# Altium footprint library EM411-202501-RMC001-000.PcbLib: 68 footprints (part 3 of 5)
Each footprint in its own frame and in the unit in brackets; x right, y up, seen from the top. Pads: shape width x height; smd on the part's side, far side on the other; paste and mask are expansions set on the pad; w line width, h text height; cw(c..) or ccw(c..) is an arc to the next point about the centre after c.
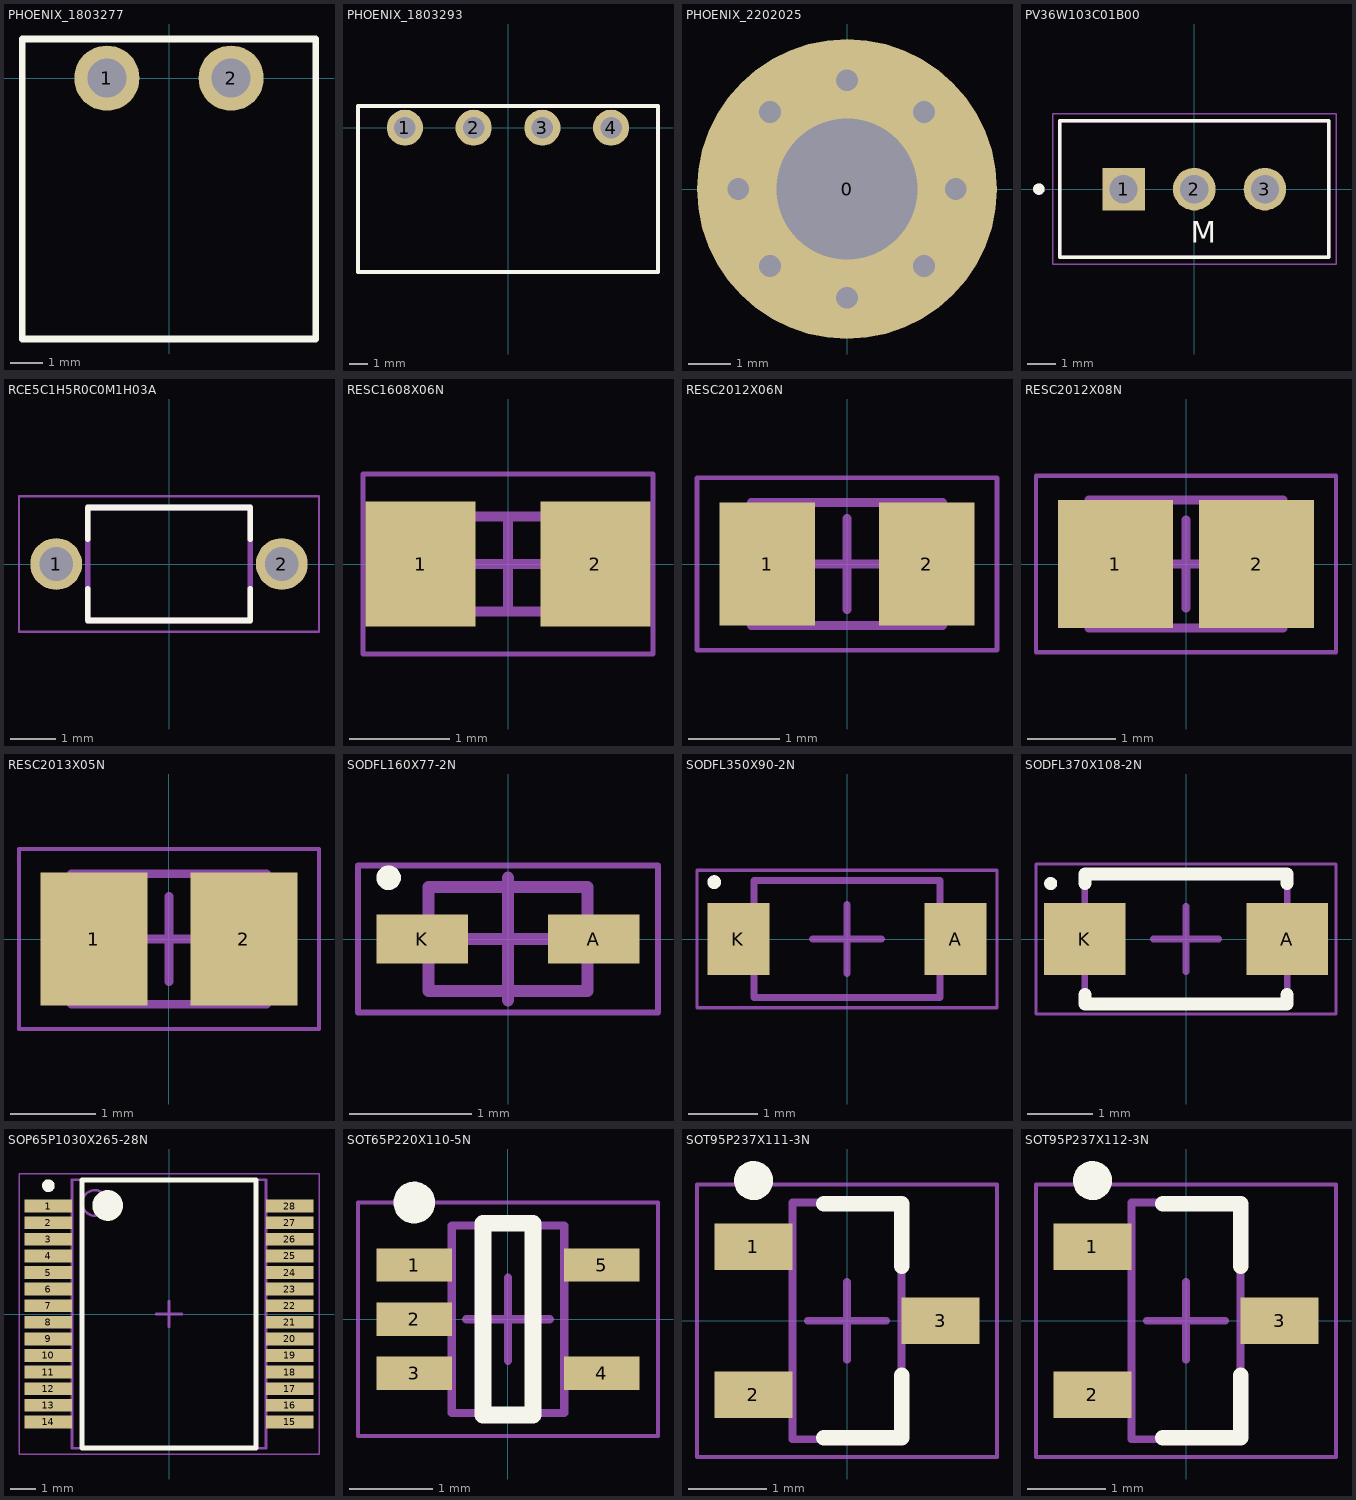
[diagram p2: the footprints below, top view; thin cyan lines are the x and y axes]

## PHOENIX_1803277 [mm] "PCB header - MC 1,5/ 2-G-3,81"
height 7.25
pads (2):
  round 2 hole 1.2: 1(-1.905,0) 2(1.905,0)
Top Overlay:
  lines w0.2: -4.505,-8 4.505,-8 4.505,1.2 -4.505,1.2 -4.505,-8
3D body "pxc_1803277_05_MC-1-5-2-G-3-81_3D.stp": height 7.25, standoff -3.4, extent -4.505,-8 4.505,1.3

## PHOENIX_1803293 [mm] "PCB header - MC 1,5/ 4-G-3,81"
height 7.25
pads (4):
  round 2 hole 1.2: 1(-5.715,0) 2(-1.905,0) 3(1.905,0) 4(5.715,0)
Top Overlay:
  lines w0.2: -8.315,-8 8.315,-8 8.315,1.2 -8.315,1.2 -8.315,-8
3D body "pxc_1803293_05_MC-1-5-4-G-3-81_3D.stp": height 7.25, standoff -3.4, extent -8.315,-8 8.315,1.3

## PHOENIX_2202025 [mm] "PE Contact Level 1"
height 8
pads (1):
  round 7 hole 3.3: 0(0,0)
via 1.796,-1.796 diameter 1.016 hole 0.508
via 2.54,0 diameter 1.016 hole 0.508
via -1.796,-1.796 diameter 1.016 hole 0.508
via 0,-2.54 diameter 1.016 hole 0.508
via -1.796,1.796 diameter 1.016 hole 0.508
via -2.54,0 diameter 1.016 hole 0.508
via 1.796,1.796 diameter 1.016 hole 0.508
via 0,2.54 diameter 1.016 hole 0.508

## PV36W103C01B00 [mm]
pads (3):
  rect 1.508x1.508 / inner round 1.508 / far side rect 1.508x1.508 hole 1: 1(-2.5,0)
  round 1.508 hole 1: 2(0,0) 3(2.5,0)
Top Overlay:
  circle w0.2: c-5.5,0 r0.1
  lines w0.127: -4.765,-2.41 4.765,-2.41 4.765,2.42 -4.765,2.42 -4.765,-2.41
  text "M" at -0.127,-1.905 h0.76
Mechanical 13:
  circle w0.2: c-5.5,0 r0.1
  lines w0.127: -4.765,-2.41 4.765,-2.41 4.765,2.42 -4.765,2.42 -4.765,-2.41
Mechanical 15:
  lines w0.05: -5.015,-2.66 5.015,-2.66 5.015,2.67 -5.015,2.67 -5.015,-2.66
3D body "step_temp.STEP": height 11.55, standoff -7.72, extent -4.765,-2.41 4.765,2.42

## RCE5C1H5R0C0M1H03A [mm] "5 pF ±0.25pF 50V Ceramic Capacitor C0G, NP0 Radial"
pads (2):
  round 1.15 hole 0.75: 1(-2.5,0) 2(2.5,0)
Top Overlay:
  lines w0.127: -1.8,-0.547 -1.8,-1.25 1.8,-1.25 1.8,-0.547 ; -1.8,0.547 -1.8,1.25 1.8,1.25 1.8,0.547
Mechanical 13:
  lines w0.127: -1.8,-1.25 1.8,-1.25 1.8,1.25 -1.8,1.25 -1.8,-1.25
Mechanical 15:
  lines w0.05: -3.325,-1.5 3.325,-1.5 3.325,1.5 -3.325,1.5 -3.325,-1.5

## RESC1608X06N [mm] "Chip Resistor, 2-Leads, Body 1.60x0.85mm, IPC Medium Density"
height 0.55
pads (2):
  rect 1.1x1.25 smd: 1(-0.875,0) 2(0.875,0)
Top Courtyard:
  lines w0.05: -1.45,-0.9 1.45,-0.9 1.45,0.9 -1.45,0.9 -1.45,-0.9
  lines w0.1: -0.475,0 0.475,0 ; 0,-0.475 0,0.475
Mechanical 13:
  lines w0.1: -0.85,-0.475 0.85,-0.475 0.85,0.475 -0.85,0.475 -0.85,-0.475
3D body "RESC1608X06N.step": height 0.55, standoff 0, extent -0.85,-0.475 0.85,0.475

## RESC2012X06N [mm] "Chip Resistor, 2-Leads, Body 2.00x1.25mm, IPC Medium Density"
height 0.6
pads (2):
  rect 1.05x1.35 smd: 1(-0.875,0) 2(0.875,0)
Top Courtyard:
  lines w0.05: -1.65,-0.95 -1.65,0.95 1.65,0.95 1.65,-0.95 -1.65,-0.95
  lines w0.1: -0.5,0 0.5,0 ; 0,-0.5 0,0.5
Mechanical 13:
  lines w0.1: -1.05,-0.675 -1.05,0.675 1.05,0.675 1.05,-0.675 -1.05,-0.675
3D body "RESC2012X06N.step": height 0.6, standoff 0, extent -1.05,-0.675 1.05,0.675

## RESC2012X08N [mm] "Chip Resistor, 2-Leads, Body 2.00x1.25mm, IPC Medium Density"
height 0.75
pads (2):
  rect 1.3x1.45 smd: 1(-0.8,0) 2(0.8,0)
Top Courtyard:
  lines w0.05: -1.7,-1 1.7,-1 1.7,1 -1.7,1 -1.7,-1
  lines w0.1: -0.5,0 0.5,0 ; 0,-0.5 0,0.5
Mechanical 13:
  lines w0.1: -1.1,-0.725 1.1,-0.725 1.1,0.725 -1.1,0.725 -1.1,-0.725
3D body "RESC2012X08N.step": height 0.75, standoff 0, extent -1.1,-0.725 1.1,0.725

## RESC2013X05N [mm] "Chip Resistor, 2-Leads, Body 2.03x1.32mm, IPC Medium Density"
height 0.54
pads (2):
  rect 1.25x1.55 smd: 1(-0.875,0) 2(0.875,0)
Top Courtyard:
  lines w0.05: -1.75,-1.05 -1.75,1.05 1.75,1.05 1.75,-1.05 -1.75,-1.05
  lines w0.1: -0.5,0 0.5,0 ; 0,-0.5 0,0.5
Mechanical 13:
  lines w0.1: -1.14,-0.76 -1.14,0.76 1.14,0.76 1.14,-0.76 -1.14,-0.76
3D body "RESC2013X05N.step": height 0.53, standoff 0, extent -1.14,-0.76 1.14,0.76

## SODFL160X77-2N [mm] "SODFL, 2-Leads, Body 0.80x1.60mm, IPC Medium Density"
height 0.77
pads (2):
  rect 0.75x0.4 smd: A(0.7,0) K(-0.7,0)
Top Overlay:
  circle w0.1: c-0.975,0.5 r0.05
Top Courtyard:
  lines w0.05: -1.225,-0.6 -1.225,0.6 1.225,0.6 1.225,-0.6 -1.225,-0.6
  lines w0.1: -0.5,0 0.5,0 ; 0,-0.5 0,0.5
Mechanical 13:
  lines w0.1: -0.65,-0.425 -0.65,0.425 0.65,0.425 0.65,-0.425 -0.65,-0.425
3D body "SODFL160X77-2N.step": height 0.77, standoff 0, extent -0.8,-0.425 0.8,0.425

## SODFL350X90-2N [mm] "SODFL, 2-Leads, Body 1.60x3.50mm, IPC Medium Density"
height 0.9
pads (2):
  rect 0.9x1.05 smd: A(1.575,0) K(-1.575,0)
Top Overlay:
  circle w0.1: c-1.925,0.825 r0.05
Top Courtyard:
  lines w0.05: -2.175,-1 2.175,-1 2.175,1 -2.175,1 -2.175,-1
  lines w0.1: -0.5,0 0.5,0 ; 0,-0.5 0,0.5
Mechanical 13:
  lines w0.1: -1.35,-0.85 1.35,-0.85 1.35,0.85 -1.35,0.85 -1.35,-0.85
3D body "SODFL350X90-2N.step": height 0.9, standoff 0, extent -1.75,-0.85 1.75,0.85

## SODFL370X108-2N [mm] "SODFL, 2-Leads, Body 1.85x3.70mm, IPC Medium Density"
height 1.08
pads (2):
  rect 1.25x1.1 smd: A(1.55,0) K(-1.55,0)
Top Overlay:
  circle w0.1: c-2.075,0.85 r0.05
  lines w0.2: -1.55,-0.85 -1.55,-1 1.55,-1 1.55,-0.85 ; -1.55,0.85 -1.55,1 1.55,1 1.55,0.85
Top Courtyard:
  lines w0.05: -2.3,-1.15 -2.3,1.15 2.3,1.15 2.3,-1.15 -2.3,-1.15
  lines w0.1: -0.5,0 0.5,0 ; 0,-0.5 0,0.5
Mechanical 13:
  lines w0.1: -1.55,-1 -1.55,1 1.55,1 1.55,-1 -1.55,-1
3D body "SODFL370X108-2N.step": height 1.08, standoff 0, extent -1.85,-1 1.85,1

## SOP65P1030X265-28N [mm] "SOP, 28-Leads, Body 10.30x7.50mm, Pitch 0.65mm, IPC Medium Density"
height 2.65
pads (28):
  rect 1.85x0.5 smd: 1(-4.725,4.225) 2(-4.725,3.575) 3(-4.725,2.925) 4(-4.725,2.275) 5(-4.725,1.625) 6(-4.725,0.975) 7(-4.725,0.325) 8(-4.725,-0.325) 9(-4.725,-0.975) 10(-4.725,-1.625) 11(-4.725,-2.275) 12(-4.725,-2.925) 13(-4.725,-3.575) 14(-4.725,-4.225) 15(4.725,-4.225) 16(4.725,-3.575) 17(4.725,-2.925) 18(4.725,-2.275) 19(4.725,-1.625) 20(4.725,-0.975) 21(4.725,-0.325) 22(4.725,0.325) 23(4.725,0.975) 24(4.725,1.625) 25(4.725,2.275) 26(4.725,2.925) 27(4.725,3.575) 28(4.725,4.225)
Top Overlay:
  circle w0.6: c-2.4,4.25 r0.3
  circle w0.25: c-4.725,5.025 r0.125
  lines w0.2: -3.4,-5.25 3.4,-5.25 3.4,5.25 -3.4,5.25 -3.4,-5.25
Top Courtyard:
  lines w0.05: -5.875,-5.5 5.875,-5.5 5.875,5.5 -5.875,5.5 -5.875,-5.5
  lines w0.1: -0.5,0 0.5,0 ; 0,-0.5 0,0.5
Mechanical 13:
  circle w0.1: c-2.9,4.35 r0.5
  lines w0.1: -3.8,-5.25 3.8,-5.25 3.8,5.25 -3.8,5.25 -3.8,-5.25
3D body "SOP65P1030X265-28N.step": height 2.65, standoff 0, extent -5.15,-5.25 5.15,5.25

## SOT65P220X110-5N [mm] "SOT23, 5-Leads, Body 2.05x2.20mm, Pitch 0.65mm, IPC Medium Density"
height 1.1
pads (5):
  rect 0.9x0.4 smd: 1(-1.125,0.65) 2(-1.125,0) 3(-1.125,-0.65) 4(1.125,-0.65) 5(1.125,0.65)
Top Overlay:
  circle w0.25: c-1.125,1.4 r0.125
  lines w0.2: -0.3,-1.15 0.3,-1.15 0.3,1.15 -0.3,1.15 -0.3,-1.15
Top Courtyard:
  lines w0.05: -1.8,-1.4 -1.8,1.4 1.8,1.4 1.8,-1.4 -1.8,-1.4
  lines w0.1: -0.5,0 0.5,0 ; 0,-0.5 0,0.5
Mechanical 13:
  lines w0.1: -0.675,-1.125 -0.675,1.125 0.675,1.125 0.675,-1.125 -0.675,-1.125
3D body "SOT65P220X110-5N.step": height 1.1, standoff 0, extent -1.2,-1.125 1.2,1.125

## SOT95P237X111-3N [mm] "SOT23, 3-Leads, Body 2.92x2.37mm, Pitch 0.95mm, IPC Medium Density"
height 1.11
pads (3):
  rect 1x0.6 smd: 1(-1.2,0.95) 2(-1.2,-0.95) 3(1.2,0)
Top Overlay:
  circle w0.25: c-1.2,1.8 r0.125
  lines w0.2: -0.3,-1.5 0.7,-1.5 0.7,-0.7 ; -0.3,1.5 0.7,1.5 0.7,0.7
Top Courtyard:
  lines w0.05: -1.925,-1.75 1.925,-1.75 1.925,1.75 -1.925,1.75 -1.925,-1.75
  lines w0.1: -0.5,0 0.5,0 ; 0,-0.5 0,0.5
Mechanical 13:
  lines w0.1: -0.7,-1.52 0.7,-1.52 0.7,1.52 -0.7,1.52 -0.7,-1.52
3D body "SOT95P237X111-3N.step": height 1.11, standoff 0, extent -1.32,-1.52 1.32,1.52

## SOT95P237X112-3N [mm] "SOT23, 3-Leads, Body 2.92x2.37mm, Pitch 0.95mm, IPC Medium Density"
height 1.12
pads (3):
  rect 1x0.6 smd: 1(-1.2,0.95) 2(-1.2,-0.95) 3(1.2,0)
Top Overlay:
  circle w0.25: c-1.2,1.8 r0.125
  lines w0.2: -0.3,-1.5 0.7,-1.5 0.7,-0.7 ; -0.3,1.5 0.7,1.5 0.7,0.7
Top Courtyard:
  lines w0.05: -1.925,-1.75 1.925,-1.75 1.925,1.75 -1.925,1.75 -1.925,-1.75
  lines w0.1: -0.5,0 0.5,0 ; 0,-0.5 0,0.5
Mechanical 13:
  lines w0.1: -0.7,-1.52 0.7,-1.52 0.7,1.52 -0.7,1.52 -0.7,-1.52
3D body "SOT95P237X112-3N.step": height 1.12, standoff 0, extent -1.37,-1.52 1.37,1.52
